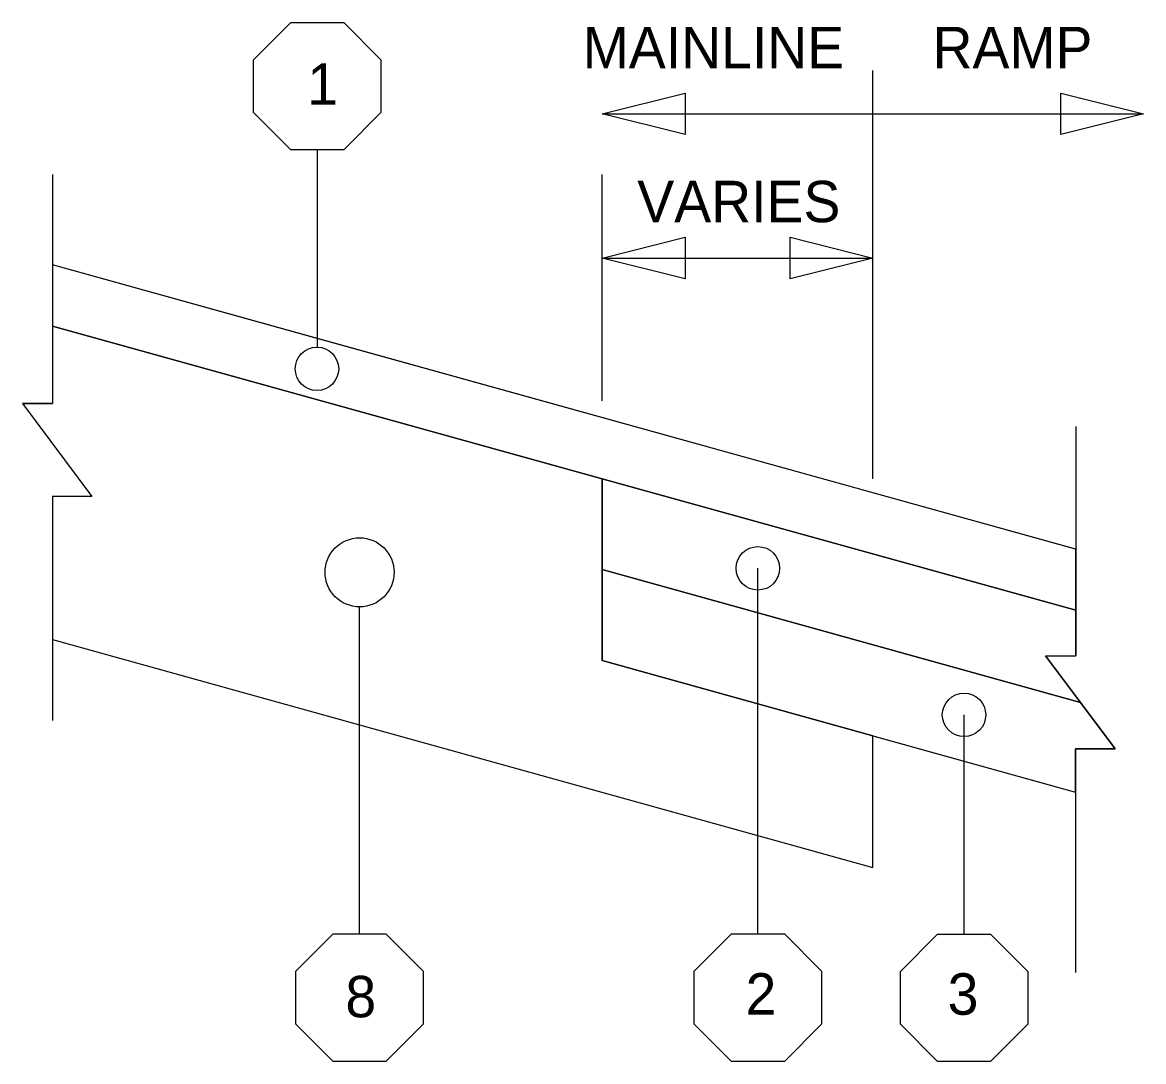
# Model space of a CAD drawing. Extents: x 4932 to 5887, y 4809 to 5473.
# Drawn here: x 4936.08 to 4966.07, y 5040.24 to 5068.02 of the extents above; entities that cross this region are included whole.
import ezdxf

# ---------------------------------------------------------------- set-up
doc = ezdxf.new("R2010")
doc.units = 0
for name, color, linetype in [('RD_QTY_Intermediate', 7, 'Continuous'), ('RD_QTY_Surf_Course', 7, 'Continuous'), ('RD_SHT_Typical', 7, 'Continuous'), ('RD_TX_TypSect', 7, 'Continuous'), ('RD_XS_ExPaveRet', 7, 'Continuous'), ('TERMINATOR', 7, 'Continuous'), ('typical_on', 7, 'Continuous')]:
    doc.layers.add(name, color=color, linetype=linetype)

# ---------------------------------------------------------------- blocks, each defined once
blk = doc.blocks.new('AH')
at = {"layer": 'TERMINATOR'}
blk.add_lwpolyline([(-6, 1.5), (0, 0), (-6, -1.5)], close=True, dxfattribs=at)

msp = doc.modelspace()

# ---------------------------------------------------------------- linework, layer by layer
at = {"layer": 'RD_QTY_Intermediate'}
for p, q in [((4964.384, 5049.837), (4951.587, 5053.392)), ((4951.587, 5053.392), (4951.587, 5050.961)), ((4951.587, 5050.961), (4958.828, 5048.95)), ((4965.309, 5048.601), (4964.384, 5049.837)), ((4958.828, 5048.95), (4964.252, 5047.443)), ((4964.252, 5047.443), (4964.252, 5048.601)), ((4964.252, 5048.601), (4965.309, 5048.601))]:
    msp.add_line(p, q, dxfattribs=at)
msp.add_circle((4961.267, 5049.507), 0.581, dxfattribs=at)
at = {"layer": 'RD_QTY_Surf_Course'}
for p, q in [((4964.253, 5052.304), (4951.587, 5055.822)), ((4951.587, 5055.822), (4951.587, 5053.392)), ((4951.587, 5053.392), (4964.384, 5049.837)), ((4964.253, 5051.087), (4964.253, 5052.304)), ((4963.448, 5051.087), (4964.253, 5051.087)), ((4964.384, 5049.837), (4963.448, 5051.087))]:
    msp.add_line(p, q, dxfattribs=at)
msp.add_circle((4955.754, 5053.427), 0.581, dxfattribs=at)
at = {"layer": 'RD_SHT_Typical'}
for p, q in [((4936.886, 5063.961), (4936.885, 5057.833)), ((4964.282, 5053.933), (4936.885, 5061.543)), ((4936.885, 5059.906), (4964.253, 5052.304)), ((4936.08, 5057.833), (4937.94, 5055.347)), ((4936.08, 5057.833), (4936.885, 5057.833)), ((4964.254, 5057.215), (4964.253, 5051.087)), ((4936.884, 5055.347), (4936.883, 5049.362)), ((4937.94, 5055.347), (4936.884, 5055.347)), ((4951.587, 5053.392), (4964.384, 5049.837)), ((4951.587, 5050.961), (4964.252, 5047.443)), ((4963.448, 5051.087), (4965.309, 5048.601)), ((4963.448, 5051.087), (4964.253, 5051.087)), ((4964.252, 5048.601), (4964.251, 5042.616)), ((4965.309, 5048.601), (4964.252, 5048.601))]:
    msp.add_line(p, q, dxfattribs=at)
at = {"layer": 'RD_TX_TypSect'}
for p, q in [((4958.828, 5055.822), (4958.828, 5066.735)), ((4951.587, 5065.578), (4958.828, 5065.578)), ((4958.828, 5065.578), (4966.069, 5065.578)), ((4943.967, 5064.614), (4943.967, 5059.342)), ((4951.587, 5057.903), (4951.587, 5063.961)), ((4951.587, 5061.724), (4958.828, 5061.724)), ((4936.885, 5061.543), (4936.885, 5059.906)), ((4936.885, 5059.906), (4951.587, 5055.822)), ((4951.587, 5055.822), (4951.587, 5053.392)), ((4951.587, 5055.822), (4964.253, 5052.304)), ((4964.253, 5052.304), (4964.254, 5053.941)), ((4951.587, 5053.392), (4951.587, 5050.961)), ((4955.754, 5043.651), (4955.754, 5053.427)), ((4945.099, 5043.653), (4945.099, 5052.397)), ((4961.267, 5043.647), (4961.267, 5049.507))]:
    msp.add_line(p, q, dxfattribs=at)
msp.add_lwpolyline([(4964.254, 5053.941), (4943.967, 5059.576), (4936.885, 5061.543)], dxfattribs=at)
for centre, radius in [((4943.959, 5058.761), 0.581), ((4943.959, 5058.761), 0.581), ((4945.099, 5053.32), 0.923), ((4955.754, 5053.427), 0.581), ((4961.267, 5049.507), 0.581)]:
    msp.add_circle(centre, radius, dxfattribs=at)
at = {"layer": 'RD_XS_ExPaveRet'}
for p, q in [((4936.885, 5059.906), (4951.587, 5055.822)), ((4951.587, 5055.822), (4936.885, 5059.906)), ((4936.885, 5059.906), (4936.885, 5057.833)), ((4936.885, 5057.833), (4936.08, 5057.833)), ((4936.08, 5057.833), (4937.94, 5055.347)), ((4951.587, 5055.822), (4951.587, 5050.961)), ((4936.884, 5055.347), (4936.883, 5051.525)), ((4937.94, 5055.347), (4936.884, 5055.347)), ((4936.883, 5051.525), (4958.828, 5045.429)), ((4936.883, 5051.525), (4958.828, 5045.429)), ((4958.828, 5048.95), (4951.587, 5050.961)), ((4958.828, 5045.429), (4958.828, 5048.95)), ((4958.828, 5045.429), (4958.828, 5048.95))]:
    msp.add_line(p, q, dxfattribs=at)
msp.add_lwpolyline([(4951.587, 5050.961), (4951.587, 5053.392), (4951.587, 5055.822)], dxfattribs=at)
msp.add_circle((4945.099, 5053.32), 0.923, dxfattribs=at)
at = {"layer": 'typical_on'}
for points in [[(4945.671, 5067.025), (4945.671, 5065.613), (4944.673, 5064.614), (4943.261, 5064.614), (4942.262, 5065.613), (4942.262, 5067.025), (4943.261, 5068.023), (4944.673, 5068.023)], [(4946.803, 5042.654), (4946.803, 5041.242), (4945.805, 5040.244), (4944.393, 5040.244), (4943.395, 5041.242), (4943.395, 5042.654), (4944.393, 5043.653), (4945.805, 5043.653)], [(4957.458, 5042.653), (4957.458, 5041.241), (4956.46, 5040.243), (4955.048, 5040.243), (4954.05, 5041.241), (4954.05, 5042.653), (4955.048, 5043.651), (4956.46, 5043.651)], [(4962.971, 5042.649), (4962.971, 5041.237), (4961.973, 5040.239), (4960.561, 5040.239), (4959.563, 5041.237), (4959.563, 5042.649), (4960.561, 5043.647), (4961.973, 5043.647)]]:
    msp.add_lwpolyline(points, close=True, dxfattribs=at)

# ---------------------------------------------------------------- block references
at = {"layer": 'RD_QTY_Surf_Course', "xscale": 0.3695692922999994, "yscale": 0.3695692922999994, "rotation": 180}
for p in [(4951.587, 5065.578), (4951.587, 5061.724)]:
    msp.add_blockref('AH', p, dxfattribs=at)
at = {"layer": 'TERMINATOR', "xscale": 0.3692401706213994, "yscale": 0.36924017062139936, "rotation": -0.0014178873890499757}
for p in [(4966.069, 5065.578), (4958.828, 5061.724)]:
    msp.add_blockref('AH', p, dxfattribs=at)

# ---------------------------------------------------------------- texts
at = {"layer": 'RD_TX_TypSect'}
for s, height, p in [('MAINLINE', 1.1076, (4951.066, 5066.797)), ('RAMP', 1.1076, (4960.423, 5066.797)), ('1', 1.108, (4943.698, 5065.821)), ('VARIES', 1.1076, (4952.527, 5062.681)), ('8', 1.108, (4944.719, 5041.423)), ('2', 1.108, (4955.422, 5041.494)), ('3', 1.108, (4960.828, 5041.491))]:
    msp.add_text(s, height=height, dxfattribs=at).set_placement(p)

doc.saveas('drawing.dxf')
